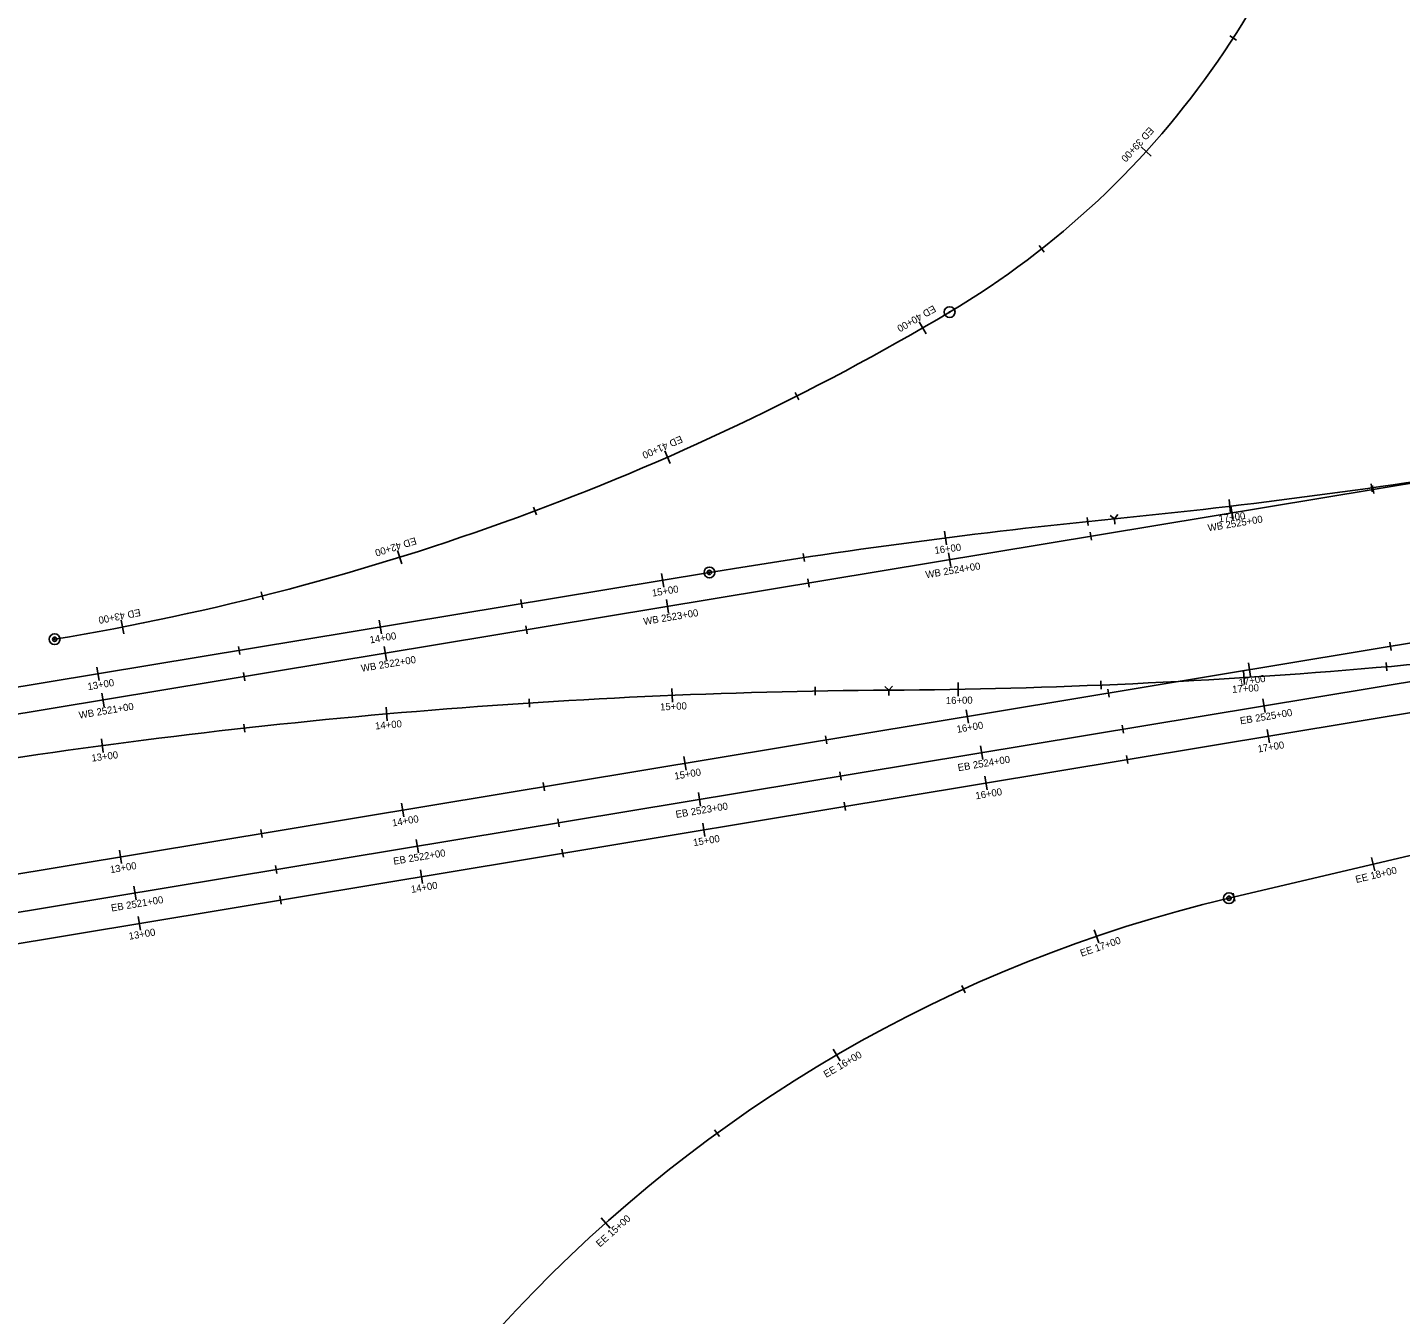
# Model space of a CAD drawing. Extents: x 950864 to 953360, y 1126381 to 1128045.
# Drawn here: x 952128.6 to 952608.5, y 1127119 to 1127568.8 of the extents above; entities that cross this region are included whole.
import ezdxf

# ---------------------------------------------------------------- set-up
doc = ezdxf.new("R2010")
doc.units = 0
for name, color, linetype in [('Existing', 7, 'Continuous'), ('LFILL_P', 7, 'Continuous'), ('North Crossover', 7, 'Continuous')]:
    doc.layers.add(name, color=color, linetype=linetype)

msp = doc.modelspace()

# ---------------------------------------------------------------- linework, layer by layer
at = {"layer": 'Existing'}
for p, q in [((950872.52, 1127121.15), (953338.85, 1127530.05)), ((950883.69, 1127053.72), (953350.03, 1127462.62)), ((952548.55, 1127264.51), (953008.86, 1127373.31))]:
    msp.add_line(p, q, dxfattribs=at)
for points in [[(952551.25, 1127564.37), (952548.83, 1127565.93)], [(952521.43, 1127523.9), (952517.88, 1127527.13)], [(952484.01, 1127490.34), (952482.23, 1127492.6)], [(952442.7, 1127461.76), (952440.3, 1127465.92)], [(952398.2, 1127438.74), (952396.9, 1127441.31)], [(952353.3, 1127416.48), (952351.38, 1127420.88)], [(952598.71, 1127408.8), (952599.18, 1127405.96)], [(952306.52, 1127398.53), (952305.51, 1127401.23)], [(952549.23, 1127401.57), (952550.02, 1127396.83)], [(952500.06, 1127392.44), (952500.53, 1127389.6)], [(952259.43, 1127381.39), (952258, 1127385.98)], [(952450.58, 1127385.21), (952451.36, 1127380.48)], [(952401.41, 1127376.09), (952401.88, 1127373.24)], [(952210.95, 1127368.74), (952210.24, 1127371.54)], [(952351.92, 1127368.86), (952352.71, 1127364.12)], [(952162.25, 1127356.93), (952161.34, 1127361.64)], [(952302.75, 1127359.73), (952303.22, 1127356.89)], [(952253.27, 1127352.5), (952254.06, 1127347.76)], [(952204.1, 1127343.37), (952204.57, 1127340.53)], [(952154.62, 1127336.14), (952155.4, 1127331.41)], [(952560.41, 1127334.14), (952561.19, 1127329.4)], [(952511.24, 1127325.01), (952511.71, 1127322.17)], [(952461.76, 1127317.78), (952462.54, 1127313.05)], [(952412.59, 1127308.66), (952413.06, 1127305.82)], [(952363.1, 1127301.43), (952363.89, 1127296.69)], [(952313.93, 1127292.3), (952314.4, 1127289.46)], [(952264.45, 1127285.07), (952265.23, 1127280.34)], [(952215.28, 1127275.95), (952215.75, 1127273.11)], [(952598.42, 1127278.76), (952599.52, 1127274.09)], [(952165.8, 1127268.72), (952166.58, 1127263.98)], [(952549.98, 1127266.33), (952550.64, 1127263.53)], [(952501.48, 1127253.46), (952503.03, 1127248.91)], [(952455.22, 1127234.03), (952456.41, 1127231.41)], [(952410.24, 1127211.78), (952412.66, 1127207.63)], [(952368.75, 1127183.54), (952370.45, 1127181.21)], [(952329.09, 1127152.8), (952332.29, 1127149.22)]]:
    msp.add_lwpolyline(points, dxfattribs=at)
for centre, radius in [((952450.92, 1127469.36), 1.89), ((952450.92, 1127469.36), 0.154), ((952138.1, 1127355.03), 1.89), ((952138.1, 1127355.03), 0.744), ((952138.1, 1127355.03), 0.154), ((952548.55, 1127264.51), 1.89), ((952548.55, 1127264.51), 0.744), ((952548.55, 1127264.51), 0.154)]:
    msp.add_circle(centre, radius, dxfattribs=at)
for centre, radius, start, end in [((952297.58, 1127727.21), 300, 300.7397, 39.5561), ((951990.9, 1128242.91), 900, 279.4135, 300.73975), ((952663.56, 1126777.92), 500, 103.2987, 170.1752)]:
    msp.add_arc(centre, radius, start, end, dxfattribs=at)
at = {"layer": 'LFILL_P'}
for p, q in [((951976.7, 1127248.38), (952619.55, 1127354.96)), ((951901.7, 1127211.62), (952623.47, 1127331.29))]:
    msp.add_line(p, q, dxfattribs=at)
for points in [[(952604.83, 1127353.98), (952605.3, 1127351.14)], [(952555.34, 1127346.75), (952556.13, 1127342.02)], [(952506.17, 1127337.63), (952506.65, 1127334.78)], [(952456.69, 1127330.39), (952457.48, 1127325.66)], [(952561.92, 1127323.51), (952562.7, 1127318.78)], [(952407.52, 1127321.27), (952407.99, 1127318.43)], [(952358.04, 1127314.04), (952358.82, 1127309.3)], [(952512.75, 1127314.39), (952513.22, 1127311.55)], [(952308.87, 1127304.91), (952309.34, 1127302.07)], [(952463.26, 1127307.16), (952464.05, 1127302.42)], [(952259.38, 1127297.68), (952260.17, 1127292.95)], [(952414.09, 1127298.03), (952414.56, 1127295.19)], [(952364.61, 1127290.8), (952365.4, 1127286.07)], [(952210.21, 1127288.56), (952210.69, 1127285.72)], [(952160.73, 1127281.33), (952161.52, 1127276.59)], [(952315.44, 1127281.68), (952315.91, 1127278.83)], [(952265.96, 1127274.45), (952266.74, 1127269.71)], [(952216.79, 1127265.32), (952217.26, 1127262.48)], [(952167.3, 1127258.09), (952168.09, 1127253.35)]]:
    msp.add_lwpolyline(points, dxfattribs=at)
at = {"layer": 'North Crossover'}
for p, q in [((952508.51, 1127397.1), (952507.05, 1127398.3)), ((952509.7, 1127398.56), (952508.51, 1127397.1)), ((952508.51, 1127397.1), (952508.7, 1127395.23)), ((951887.25, 1127298.82), (952366.98, 1127378.36)), ((952429.68, 1127337.23), (952428.34, 1127338.55)), ((952431, 1127338.57), (952429.68, 1127337.23)), ((952429.68, 1127337.23), (952429.69, 1127335.34))]:
    msp.add_line(p, q, dxfattribs=at)
for points in [[(952598.25, 1127409.35), (952598.65, 1127406.5)], [(952548.59, 1127403.88), (952549.15, 1127399.11)], [(952499.01, 1127397.58), (952499.3, 1127394.72)], [(952449.18, 1127392.81), (952449.79, 1127388.05)], [(952399.75, 1127384.99), (952400.17, 1127382.14)], [(952350.2, 1127378.01), (952350.99, 1127373.27)], [(952301.03, 1127368.88), (952301.5, 1127366.04)], [(952251.55, 1127361.65), (952252.33, 1127356.92)], [(952202.38, 1127352.53), (952202.85, 1127349.69)], [(952152.89, 1127345.3), (952153.68, 1127340.56)], [(952553.66, 1127344.02), (952553.97, 1127339.23)], [(952603.55, 1127346.84), (952603.8, 1127343.97)], [(952353.84, 1127337.79), (952354.04, 1127333)], [(952403.89, 1127338.34), (952403.94, 1127335.46)], [(952453.87, 1127339.93), (952453.95, 1127335.13)], [(952503.83, 1127340.44), (952503.95, 1127337.56)], [(952303.92, 1127334.17), (952304.1, 1127331.3)], [(952253.95, 1127331.31), (952254.37, 1127326.53)], [(952204.24, 1127325.39), (952204.56, 1127322.53)], [(952154.46, 1127320.23), (952155.1, 1127315.47)]]:
    msp.add_lwpolyline(points, dxfattribs=at)
for centre, radius in [((952508.51, 1127397.1), 0.154), ((952366.98, 1127378.36), 1.88), ((952366.98, 1127378.36), 0.747), ((952366.98, 1127378.36), 0.156), ((952429.68, 1127337.23), 0.154)]:
    msp.add_circle(centre, radius, dxfattribs=at)
for centre, radius, start, end in [((952292.01, 1129575.37), 2189, 275.67597, 279.4135), ((952725.01, 1125218.83), 2189, 95.67597, 99.4135), ((952415.17, 1129502.18), 2165, 270.38393, 279.4135), ((952444.18, 1125172.28), 2165, 90.38393, 99.4135)]:
    msp.add_arc(centre, radius, start, end, dxfattribs=at)

# ---------------------------------------------------------------- texts
at = {"layer": 'Existing'}
for s, rotation, p in [('ED 39+00', 227.7531, (952520.73, 1127534.27)), ('ED 40+00', 210.0447, (952445.22, 1127471.87)), ('ED 41+00', 203.6785, (952356.92, 1127426.25)), ('WB 2525+00', 9.4135, (952541.38, 1127392.68)), ('ED 42+00', 197.3123, (952264.11, 1127390.7)), ('WB 2524+00', 9.4135, (952442.72, 1127376.32)), ('ED 43+00', 190.9461, (952167.9, 1127365.65)), ('WB 2523+00', 9.4135, (952344.11, 1127359.97)), ('WB 2522+00', 9.4135, (952245.41, 1127343.61)), ('WB 2521+00', 9.4135, (952146.76, 1127327.25)), ('EB 2525+00', 9.4135, (952552.64, 1127325.26)), ('EB 2524+00', 9.4135, (952453.98, 1127308.9)), ('EB 2523+00', 9.4135, (952355.37, 1127292.55)), ('EB 2522+00', 9.4135, (952256.68, 1127276.19)), ('EE 18+00', 13.2987, (952593.09, 1127269.81)), ('EB 2521+00', 9.4135, (952158.02, 1127259.84)), ('EE 17+00', 18.821, (952497.05, 1127244.03)), ('EE 16+00', 30.2802, (952407.78, 1127201.67)), ('EE 15+00', 41.7393, (952328.68, 1127142.4))]:
    msp.add_text(s, height=2.496, rotation=rotation, dxfattribs=at).set_placement(p)
at = {"layer": 'LFILL_P'}
for s, p in [('17+00', (952552.22, 1127338.64)), ('16+00', (952453.59, 1127322.29)), ('17+00', (952558.8, 1127315.41)), ('15+00', (952354.93, 1127305.93)), ('16+00', (952460.17, 1127299.05)), ('14+00', (952256.26, 1127289.58)), ('15+00', (952361.5, 1127282.69)), ('13+00', (952157.65, 1127273.23)), ('14+00', (952262.84, 1127266.34)), ('13+00', (952164.22, 1127249.99))]:
    msp.add_text(s, height=2.496, rotation=9.4135, dxfattribs=at).set_placement(p)
at = {"layer": 'North Crossover'}
for s, rotation, p in [('17+00', 6.7386, (952545.09, 1127395.92)), ('16+00', 7.2307, (952445.78, 1127384.83)), ('15+00', 9.4135, (952347.09, 1127369.9)), ('14+00', 9.4135, (952248.43, 1127353.54)), ('13+00', 9.4135, (952149.81, 1127337.2)), ('17+00', 3.6717, (952549.75, 1127336.26)), ('15+00', 2.389, (952349.76, 1127330.13)), ('16+00', 1.0253, (952449.62, 1127332.36)), ('14+00', 5.0355, (952250.22, 1127323.47)), ('13+00', 7.682, (952151.13, 1127312.22))]:
    msp.add_text(s, height=2.496, rotation=rotation, dxfattribs=at).set_placement(p)

doc.saveas('drawing.dxf')
